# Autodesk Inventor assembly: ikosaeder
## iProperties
Created: 2007-01
Part Number: ikosaeder
Cost Center: 0,48 kg
Document SubType Name: Assembly
Designer: M. Fiedler
Author: M. Fiedler
SaveDate: 2007-01-25
SaveTime: 21:26
Masse: 0,48 kg
